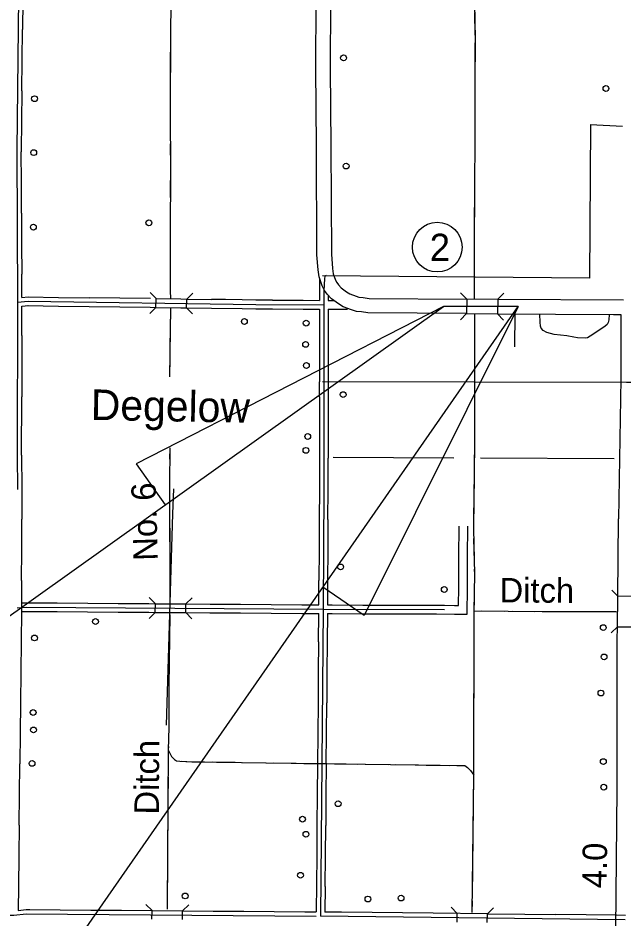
# Model space of a CAD drawing. Extents: x -4306 to 3843, y 131 to 8341.
# Drawn here: x -1926 to -255, y 1950 to 4435 of the extents above; entities that cross this region are included whole.
import ezdxf

# ---------------------------------------------------------------- set-up
doc = ezdxf.new("R2010")
doc.units = 0
for name, color, linetype in [('10', 7, 'Continuous'), ('24', 7, 'Continuous'), ('31', 7, 'Continuous'), ('32', 7, 'Continuous'), ('33', 7, 'Continuous'), ('38', 7, 'Continuous'), ('50', 7, 'Continuous'), ('52', 7, 'Continuous'), ('53', 7, 'Continuous'), ('55', 7, 'Continuous'), ('56', 7, 'Continuous'), ('57', 7, 'Continuous'), ('61', 7, 'Continuous'), ('62', 7, 'Continuous')]:
    doc.layers.add(name, color=color, linetype=linetype)

msp = doc.modelspace()

# ---------------------------------------------------------------- linework, layer by layer
at = {"layer": '10'}
for p, q in [((-1100.3, 3780.5), (-1101.9, 4080.9)), ((-1096.8, 3739), (-1100.3, 3780.5)), ((-1094.3, 3719.7), (-1096.8, 3739)), ((-1086.2, 3695.3), (-1094.3, 3719.7)), ((-1079.5, 3682.8), (-1086.2, 3695.3)), ((-1071.8, 3672), (-1079.5, 3682.8)), ((-1059.8, 3659.7), (-1071.8, 3672)), ((-1040.8, 3645.6), (-1059.8, 3659.7)), ((-686.3, 3658.5), (-686.6, 3618.5)), ((-601.1, 3657.9), (-686.2, 3658.5)), ((-600.7, 3657.9), (-601, 3617.9)), ((-252.8, 3655.5), (-600.7, 3657.9)), ((-1027.4, 3637.4), (-1040.8, 3645.6)), ((-1005, 3628.7), (-1027.4, 3637.4)), ((-991.1, 3624.8), (-1005, 3628.7)), ((-977.5, 3623.7), (-991.1, 3624.8)), ((-959.9, 3620.4), (-977.5, 3623.7)), ((-686.6, 3618.5), (-959.9, 3620.4)), ((-687.1, 3618.5), (-600.9, 3617.9)), ((-601, 3617.9), (-281, 3615.7)), ((-281, 3615.7), (-260.7, 3616)), ((-260.7, 3616), (-260.6, 3613.9)), ((-260.6, 3613.9), (-260.3, 3438.2)), ((-260.3, 3438.2), (-266.6, 3051.5)), ((-269.9, 2753.7), (-269, 2836.4)), ((-229, 2837.7), (-269, 2838.1)), ((-269.9, 2754), (-229.9, 2753.6))]:
    msp.add_line(p, q, dxfattribs=at)
for points in [[(-1101.9, 4080.9), (-1103.3, 4295.8), (-1102.5, 4483.2)], [(-1062.5, 4483.1), (-1063.3, 4295.8), (-1061.9, 4081.1)], [(-1061.9, 4081.1), (-1060.3, 3782.3), (-1057, 3743.3), (-1055.1, 3728.7), (-1049.3, 3711.2), (-1045.5, 3704), (-1041, 3697.8), (-1033.3, 3689.9), (-1018.4, 3678.8), (-1009.5, 3673.4), (-992.3, 3666.7), (-984.1, 3664.3), (-972.2, 3663.4), (-956, 3660.3), (-686.3, 3658.5)], [(-269, 2836.4), (-266.6, 3051.5)], [(-314.4, 293.8), (-314.5, 305.1), (-312.3, 441.3), (-305.4, 600.9), (-302, 628.3), (-293.8, 664.7), (-283.6, 735.2), (-284.1, 861.9), (-282.2, 1054.1), (-278.9, 1201.3), (-280.3, 1434.8), (-278.7, 1599.9), (-273.4, 1758.6), (-274.2, 1917.6), (-271, 2305.4), (-270.3, 2716.6), (-269.9, 2753.7)]]:
    msp.add_lwpolyline(points, dxfattribs=at)
at = {"layer": '31'}
for p, q in [((-1912.7, 4483.5), (-1913.6, 4402.7)), ((-1913.6, 4402.7), (-1913.6, 4402.7)), ((-1915.4, 4233.8), (-1916.2, 4149.3)), ((-1916.2, 4149.3), (-1917.1, 4070.3)), ((-1917.1, 4070.3), (-1917.1, 4065)), ((-1916.5, 3896), (-1916.3, 3811.5)), ((-1916.3, 3811.5), (-1916, 3727)), ((-1916, 3727), (-1916, 3727)), ((-1915.8, 3662.9), (-1898.4, 3664.6)), ((-1898.4, 3664.6), (-1813.9, 3663.4)), ((-1813.9, 3663.4), (-1729.4, 3662.3)), ((-1545.1, 3635.8), (-1544.8, 3659.8)), ((-1544.8, 3659.8), (-1476, 3658.9)), ((-1476, 3658.9), (-1460.2, 3658.7)), ((-1460.5, 3634.7), (-1460.2, 3658.7)), ((-1460.1, 3658.8), (-1391.5, 3657.8)), ((-1222.6, 3655.8), (-1138.1, 3655.3)), ((-1138.1, 3655.3), (-1093, 3654.9)), ((-1069, 3654.8), (-1053, 3654.7)), ((-1915.8, 3638.8), (-1897.4, 3640.6)), ((-1898.7, 3640.5), (-1814.2, 3639.4)), ((-1814.2, 3639.4), (-1729.7, 3638.3)), ((-1560.8, 3636), (-1545.1, 3635.8)), ((-1545, 3635.8), (-1476.3, 3634.9)), ((-1476.3, 3634.9), (-1460.6, 3634.7)), ((-1460.6, 3634.7), (-1391.8, 3633.8)), ((-1222.8, 3631.8), (-1222.8, 3631.8)), ((-1222.8, 3631.8), (-1138.3, 3631.2)), ((-1138.3, 3631.2), (-1093, 3630.9)), ((-1069, 3630.8), (-1015.9, 3630.4)), ((-1915.9, 3558), (-1916, 3473.5)), ((-1916, 3473.5), (-1916.1, 3389)), ((-1093.1, 3388.4), (-1093, 3429.9)), ((-1069, 3429.9), (-1069, 3429.9)), ((-1916.3, 3227.2), (-1916.1, 3389)), ((-1916.1, 3389), (-1916.1, 3389)), ((-1093.1, 3388.4), (-1093.3, 3304)), ((-1069.1, 3388.4), (-1069.3, 3303.9)), ((-1093.3, 3304), (-1093.4, 3219.5)), ((-1069.3, 3303.9), (-1069.4, 3219.4)), ((-1916.3, 3227.2), (-1915.2, 3135.7)), ((-1915.2, 3133.4), (-1915.6, 3051)), ((-1915.2, 3135.7), (-1915.2, 3133.4)), ((-1093.9, 3050.5), (-1094.3, 2966)), ((-1069.9, 3050.4), (-1070.3, 2965.9)), ((-1094.3, 2966), (-1094.7, 2881.5)), ((-1070.3, 2965.9), (-1070.7, 2881.4)), ((-1916.5, 2882), (-1916.8, 2820.3)), ((-1916.8, 2820.3), (-1917, 2796.3)), ((-1917, 2796.3), (-1917.9, 2713)), ((-1095.8, 2712.6), (-1096.5, 2628.1)), ((-1071.8, 2712.4), (-1072.5, 2627.9)), ((-1096.5, 2628.1), (-1097.2, 2543.6)), ((-1072.5, 2627.9), (-1073.2, 2543.4)), ((-1919.6, 2544), (-1920.4, 2459.6)), ((-1920.4, 2459.6), (-1921.3, 2375.1)), ((-1098.7, 2374.7), (-1099.4, 2290.2)), ((-1074.7, 2374.5), (-1075.4, 2290)), ((-1099.4, 2290.2), (-1100.1, 2205.7)), ((-1075.4, 2290), (-1076.1, 2205.5)), ((-1923, 2206.1), (-1923.9, 2121.6)), ((-1100.1, 2205.7), (-1100.1, 2205.7)), ((-1923.9, 2121.6), (-1924.7, 2037.1)), ((-1077.6, 2036.5), (-1078.2, 1966.2)), ((-1032.5, 1965.7), (-1078.2, 1966.2)), ((-948, 1964.8), (-1032.5, 1965.7)), ((-629.3, 1961.2), (-779, 1962.9)), ((-713.1, 1938.1), (-712.8, 1962.1)), ((-629.6, 1937.2), (-629.3, 1961.2)), ((-629.3, 1961.2), (-525.6, 1960)), ((-525.6, 1960), (-441.1, 1959.1)), ((-356.6, 1958.1), (-441.1, 1959.1)), ((-272.1, 1957.2), (-356.6, 1958.1)), ((-247.9, 1956.9), (-272.1, 1957.2))]:
    msp.add_line(p, q, dxfattribs=at)
for points in [[(-1914.5, 4318.3), (-1913.6, 4402.7)], [(-1915.4, 4233.8), (-1914.5, 4318.3)], [(-1916.8, 3980.5), (-1917.1, 4065)], [(-1916.5, 3896), (-1916.8, 3980.5)], [(-1915.8, 3662.9), (-1916, 3727)], [(-1074.7, 3724.2), (-1078.5, 3721.7), (-1079.5, 3714.3), (-1081.3, 3682.4), (-1081.6, 3642.9), (-1081, 3429.9), (-1081.6, 3132.7)], [(-1644.9, 3661.2), (-1729.4, 3662.3)], [(-1560.5, 3660), (-1644.9, 3661.2)], [(-1307, 3656.6), (-1353.3, 3657.3), (-1391.5, 3657.8)], [(-1222.6, 3655.8), (-1268.8, 3656.1), (-1307, 3656.6)], [(-1915.9, 3558), (-1915.8, 3638.8)], [(-1729.7, 3638.3), (-1645.3, 3637.2)], [(-1645.3, 3637.2), (-1560.8, 3636)], [(-1391.8, 3633.8), (-1307.3, 3632.6)], [(-1307.3, 3632.6), (-1269.1, 3632.1), (-1222.8, 3631.8)], [(-1069, 3429.9), (-1069, 3429.9), (-1069.1, 3388.4)], [(-1093.4, 3219.5), (-1093.6, 3135)], [(-1069.6, 3134.9), (-1069.4, 3219.4)], [(-1093.6, 3135), (-1093.6, 3132.7), (-1093.9, 3050.5)], [(-1081.6, 3132.7), (-1083, 2802.2), (-1090.3, 1954.4)], [(-1069.9, 3050.4), (-1069.6, 3132.7), (-1069.6, 3134.9)], [(-1916.1, 2966.5), (-1915.6, 3051)], [(-1916.5, 2882), (-1916.1, 2966.5)], [(-1095, 2814.3), (-1094.7, 2881.5)], [(-1070.7, 2881.4), (-1071, 2814.2)], [(-1095.8, 2712.6), (-1095.1, 2790.3)], [(-1071.1, 2790.2), (-1071.8, 2712.4)], [(-1917.9, 2713), (-1918.7, 2628.5)], [(-1918.7, 2628.5), (-1919.6, 2544)], [(-1097.2, 2543.6), (-1098, 2459.2)], [(-1074, 2459), (-1073.2, 2543.4)], [(-1098, 2459.2), (-1098.7, 2374.7)], [(-1074.7, 2374.5), (-1074, 2459)], [(-1922.2, 2290.6), (-1921.3, 2375.1)], [(-1923, 2206.1), (-1922.2, 2290.6)], [(-1100.1, 2205.7), (-1100.9, 2121.2)], [(-1076.8, 2121), (-1076.1, 2205.5)], [(-1100.9, 2121.2), (-1102.2, 1966.5)], [(-1077.6, 2036.5), (-1076.8, 2121)], [(-1924.7, 2037.1), (-1925.4, 1970.7)], [(-863.5, 1963.8), (-948, 1964.8)], [(-779, 1962.9), (-863.5, 1963.8)]]:
    msp.add_lwpolyline(points, dxfattribs=at)
at = {"layer": '32'}
for p, q in [((-1927.7, 3649.7), (-1898.5, 3652.6)), ((-708, 2946.9), (-707.4, 3031.4)), ((-684, 2946.8), (-683.4, 3031.3)), ((-708.5, 2862.4), (-708, 2946.9)), ((-684.5, 2862.3), (-684, 2946.8)), ((-708.8, 2812.9), (-708.5, 2862.4)), ((-685, 2788.9), (-684.5, 2862.3)), ((-1916.8, 2820.3), (-1818.2, 2819.6)), ((-1818.2, 2819.6), (-1733.7, 2819)), ((-1733.7, 2819), (-1649.2, 2818.4)), ((-1649.2, 2818.4), (-1564.7, 2817.8)), ((-1564.7, 2817.8), (-1546.6, 2817.6)), ((-1546.8, 2793.6), (-1546.6, 2817.6)), ((-1546.6, 2817.6), (-1480.2, 2817.1)), ((-1480.2, 2817.1), (-1462.2, 2817)), ((-1462.4, 2793), (-1462.2, 2817)), ((-1462.3, 2817), (-1395.7, 2816.5)), ((-1395.7, 2816.5), (-1311.2, 2815.9)), ((-1311.2, 2815.9), (-1226.7, 2815.3)), ((-1226.7, 2815.3), (-1142.3, 2814.7)), ((-1142.3, 2814.7), (-1095, 2814.3)), ((-1071, 2814.2), (-1057.8, 2814.1)), ((-1057.8, 2814.1), (-973.3, 2813.9)), ((-973.3, 2813.9), (-888.8, 2813.6)), ((-888.8, 2813.6), (-804.4, 2813.3)), ((-804.4, 2813.3), (-747.6, 2813.1)), ((-747.6, 2813.1), (-719.9, 2813)), ((-719.9, 2813), (-708.8, 2812.9)), ((-1928.9, 2805.9), (-1902.7, 2808.2)), ((-1917, 2796.3), (-1818.3, 2795.6)), ((-1818.3, 2795.6), (-1733.8, 2795)), ((-1733.8, 2795), (-1649.4, 2794.4)), ((-1649.4, 2794.4), (-1564.9, 2793.8)), ((-1564.9, 2793.8), (-1546.8, 2793.6)), ((-1546.9, 2793.6), (-1480.4, 2793.1)), ((-1480.4, 2793.1), (-1462.4, 2793)), ((-1462.6, 2793), (-1395.9, 2792.5)), ((-1395.9, 2792.5), (-1311.4, 2791.9)), ((-1311.4, 2791.9), (-1226.9, 2791.3)), ((-1226.9, 2791.3), (-1142.4, 2790.7)), ((-1142.4, 2790.7), (-1095.1, 2790.3)), ((-1071.1, 2790.2), (-1057.9, 2790.1)), ((-1057.9, 2790.1), (-973.4, 2789.8)), ((-973.4, 2789.8), (-888.9, 2789.6)), ((-888.9, 2789.6), (-770.3, 2789.2)), ((-770.3, 2789.2), (-719.9, 2789)), ((-719.9, 2789), (-685, 2788.9)), ((-1925.4, 1970.7), (-1903.9, 1973)), ((-1903.9, 1973), (-1893.9, 1972.9)), ((-1893.9, 1972.9), (-1809.4, 1972.3)), ((-1809.4, 1972.3), (-1724.9, 1971.6)), ((-1724.9, 1971.6), (-1640.4, 1970.9)), ((-1640.4, 1970.9), (-1555.9, 1970.2)), ((-1556.1, 1946.2), (-1555.9, 1970.2)), ((-1555.9, 1970.2), (-1471.4, 1969.5)), ((-1471.6, 1945.5), (-1471.4, 1969.5)), ((-1471.4, 1969.5), (-1386.9, 1968.8)), ((-1386.9, 1968.8), (-1302.4, 1968.1)), ((-1302.4, 1968.1), (-1218, 1967.4)), ((-1218, 1967.4), (-1133.5, 1966.7)), ((-1133.5, 1966.7), (-1102.2, 1966.5)), ((-248.2, 1944.9), (-1090.3, 1954.4))]:
    msp.add_line(p, q, dxfattribs=at)
for points in [[(-1983.5, 5826.9), (-1984.2, 5591.9), (-1978, 5580.6), (-1963.1, 5563), (-1953.4, 5550.1), (-1949.6, 5541.7), (-1948.4, 5534.6), (-1931.5, 5392.4), (-1927.1, 4704.6), (-1924.6, 4492.3), (-1929.1, 4070.4), (-1927.7, 3649.7), (-1928.3, 3227.1), (-1927.2, 3133.3)], [(-1898.5, 3652.6), (-1268.9, 3644.1)], [(-1268.9, 3644.1), (-1081.6, 3642.9)], [(-1902.7, 2808.2), (-1083, 2802.2), (-747.7, 2801.1)], [(-2400.7, 1957.8), (-1937.5, 1957.3), (-1903.3, 1961)], [(-1903.3, 1961), (-1102.5, 1954.5)]]:
    msp.add_lwpolyline(points, dxfattribs=at)
at = {"layer": '33'}
for p, q in [((-1092.9, 3715.7), (-1093, 3654.9)), ((-1069, 3668.1), (-1069, 3654.8)), ((-1093, 3630.9), (-1093, 3429.9)), ((-1069, 3630.8), (-1069, 3429.9)), ((-553.4, 3617.5), (-554.1, 3527)), ((-483.8, 3594.9), (-484, 3617.1)), ((-293.2, 3615.7), (-293.7, 3601.2)), ((-482.5, 3583.7), (-483.8, 3594.9)), ((-480.7, 3578.1), (-482.5, 3583.7)), ((-303.4, 3583.5), (-338, 3561.3)), ((-297.9, 3588.5), (-303.4, 3583.5)), ((-295.1, 3593.8), (-297.9, 3588.5)), ((-293.7, 3601.2), (-295.1, 3593.8)), ((-475.3, 3571.6), (-480.7, 3578.1)), ((-465.4, 3566.2), (-475.3, 3571.6)), ((-444.9, 3561.1), (-465.4, 3566.2)), ((-410.2, 3557), (-444.9, 3561.1)), ((-390.6, 3553.2), (-410.2, 3557)), ((-338, 3561.3), (-352.7, 3552.1)), ((-380, 3551.9), (-390.6, 3553.2)), ((-358.2, 3551.1), (-380, 3551.9)), ((-352.7, 3552.1), (-358.2, 3551.1))]:
    msp.add_line(p, q, dxfattribs=at)
at = {"layer": '38'}
for p, q in [((-1546.7, 2805.6), (-1546.7, 2805.6)), ((-1462.3, 2805), (-1462.3, 2805))]:
    msp.add_line(p, q, dxfattribs=at)
for points in [[(-1561.4, 3677), (-1544.7, 3659.8)], [(-1460.2, 3658.7), (-1443, 3675.4)], [(-1545, 3635.8), (-1562.2, 3619.1)], [(-1443.8, 3617.5), (-1460.5, 3634.7)], [(-1546.6, 2817.6), (-1563.5, 2834.7)], [(-1445.1, 2833.9), (-1462.2, 2817)], [(-1563.9, 2776.8), (-1546.8, 2793.6)], [(-1462.4, 2793), (-1445.5, 2775.9)], [(-1572.7, 1987.3), (-1555.9, 1970.2)], [(-1471.4, 1969.5), (-1454.3, 1986.3)], [(-729.6, 1979.3), (-712.8, 1962.1)], [(-629.3, 1961.2), (-612.1, 1978)]]:
    msp.add_lwpolyline(points, dxfattribs=at)
at = {"layer": '50'}
for p, q in [((-2855, 2139.1), (-750.7, 3638.5)), ((-2436.2, 918.6), (-544.5, 3638.5)), ((-750.7, 3638.5), (-1599.8, 3203.3)), ((-544.5, 3638.5), (-970, 2784.5)), ((-544.5, 3638.5), (-750.7, 3638.5)), ((-1599.8, 3203.3), (-1519.6, 3090.6)), ((-970, 2784.5), (-1083.5, 2863.4))]:
    msp.add_line(p, q, dxfattribs=at)
msp.add_circle((-767.7, 3802.1), 68.6, dxfattribs=at)
at = {"layer": '52'}
for p, q in [((-1055.1, 3222.1), (-721.9, 3220.4)), ((-648, 3220), (-279.3, 3218.1))]:
    msp.add_line(p, q, dxfattribs=at)
at = {"layer": '53'}
msp.add_line((-344.8, 4140.3), (-256.2, 4135.9), dxfattribs=at)
for points in [[(-344.8, 4140.3), (-347.2, 3716.3)], [(-347.2, 3716.3), (-1085.2, 3722.9)], [(506.8, 3428.7), (-245, 3428.6), (-1084.8, 3430.5)]]:
    msp.add_lwpolyline(points, dxfattribs=at)
at = {"layer": '55'}
msp.add_lwpolyline([(-272.1, 2795.3), (-477.6, 2794.8), (-665.7, 2797)], dxfattribs=at)
at = {"layer": '56'}
for points in [[(-1504.4, 4478.2), (-1505.2, 4388.9), (-1506, 4177.7), (-1505.1, 4012.5), (-1506.2, 3840.6), (-1506.1, 3682.7), (-1505.3, 3659.3)], [(-664.9, 3658.3), (-664.8, 3769), (-664.2, 3999.1), (-663.1, 4070.7), (-663.3, 4248.8), (-662.5, 4377), (-664.1, 4475.7)], [(-662.7, 4387), (-663.7, 4450.4)], [(-1504.9, 4425.4), (-1505.2, 4388.9), (-1505.3, 4362)], [(-662.9, 4302.5), (-662.6, 4365.9)], [(-1505.4, 4340.9), (-1505.7, 4277.5)], [(-663.2, 4218.1), (-663.3, 4248.8), (-663.1, 4281.4)], [(-1505.7, 4256.4), (-1506, 4193)], [(-663.2, 4165.2), (-663.2, 4196.9)], [(-1506, 4171.9), (-1505.6, 4108.6)], [(-663.1, 4133.6), (-663.2, 4165.2)], [(-663.4, 4049.1), (-663.1, 4070.7), (-663.1, 4112.4)], [(-1505.5, 4087.4), (-1505.2, 4024.1)], [(-664.3, 3964.6), (-664.2, 3999.1), (-663.7, 4028)], [(-1505.2, 4002.9), (-1505.4, 3971.3)], [(-1505.4, 3971.3), (-1505.6, 3939.6)], [(-664.5, 3880.1), (-664.3, 3943.5)], [(-1505.7, 3918.5), (-1506.1, 3855.1)], [(-664.7, 3795.6), (-664.5, 3859)], [(-1506.2, 3834), (-1506.2, 3770.6)], [(-664.8, 3711.1), (-664.8, 3769), (-664.8, 3774.5)], [(-1506.1, 3749.5), (-1506.1, 3686.1)], [(-664.9, 3658.3), (-664.9, 3690)], [(-1504.5, 3635.3), (-1507.7, 3443.8)], [(-1504.5, 3635.3), (-1505, 3603.6)], [(-664.2, 3429.5), (-663.8, 3599.9), (-664.2, 3618.3)], [(-663.9, 3566.8), (-663.8, 3599.9), (-664.2, 3618.3)], [(-1505.4, 3582.5), (-1506.5, 3519.1)], [(-664.1, 3482.3), (-663.9, 3545.6)], [(-1506.8, 3498), (-1507.7, 3443.8)], [(-664.2, 3429.5), (-664.2, 3461.2)], [(-665.7, 2797), (-664.4, 2899.3), (-666.9, 3024.6), (-664.2, 3269.6), (-664.2, 3429.5)], [(-664.2, 3356.7), (-664.2, 3420.1)], [(-664.2, 3303.9), (-664.2, 3335.6)], [(-664.2, 3272.2), (-664.2, 3303.9)], [(-1507.1, 3248), (-1507.6, 3146.3), (-1506.3, 2829.3)], [(-1507.1, 3248), (-1507.2, 3216.3)], [(-665.1, 3187.7), (-664.4, 3251.1)], [(-1507.3, 3195.2), (-1507.6, 3146.3), (-1507.5, 3131.8)], [(-666, 3103.2), (-665.3, 3166.6)], [(-1496.8, 3135), (-1498.9, 3065.5)], [(-1507.5, 3110.7), (-1507.2, 3047.3)], [(-666.8, 3018.8), (-666.9, 3024.6), (-666.3, 3082.1)], [(-1498.9, 3065.5), (-1516.5, 2482)], [(-1507.1, 3026.2), (-1506.9, 2962.9)], [(-665.1, 2934.3), (-666.4, 2997.6)], [(-1506.8, 2941.7), (-1506.5, 2878.4)], [(-665, 2849.8), (-664.4, 2899.3), (-664.7, 2913.2)], [(-1506.4, 2857.2), (-1506.3, 2829.3)], [(-665.7, 2797), (-665.3, 2828.7)], [(-1506.6, 2786.8), (-1509.9, 2594.6), (-1509.8, 2476)], [(-1506.6, 2786.8), (-1507.1, 2755.1)], [(-671, 1965), (-666.9, 2343.9), (-665.7, 2797)], [(-276, 2795.3), (-477.6, 2794.8), (-665.7, 2797)], [(-665.7, 2778.2), (-665.7, 2797)], [(-582.3, 2796), (-645.6, 2796.8)], [(-497.8, 2795), (-561.1, 2795.8)], [(-413.3, 2795), (-476.7, 2794.8)], [(-328.8, 2795.2), (-392.2, 2795)], [(-276, 2795.3), (-307.7, 2795.2)], [(-1507.5, 2734), (-1508.6, 2670.6)], [(-666, 2693.7), (-665.8, 2757.1)], [(-666.2, 2609.2), (-666, 2672.6)], [(-1508.9, 2649.5), (-1509.9, 2594.6), (-1509.9, 2586.2)], [(-666.4, 2524.7), (-666.2, 2588.1)], [(-1509.8, 2565), (-1509.8, 2501.7)], [(-666.6, 2471.9), (-666.5, 2503.6)], [(-1509.8, 2476), (-1510.9, 2414), (-1514.5, 1974.3)], [(-1509.8, 2476), (-1510.4, 2444.3)], [(-1509.8, 2480.5), (-1509.8, 2476)], [(-666.7, 2440.2), (-666.6, 2471.9)], [(-1510.7, 2423.2), (-1510.9, 2414), (-1511.3, 2359.8)], [(-1510.9, 2414), (-1501.8, 2396), (-1493.5, 2387.1), (-1488, 2383.9), (-1479.1, 2383), (-1445.5, 2381.2), (-692, 2370.4), (-684, 2365.6), (-675.6, 2357.3), (-666.9, 2343.9)], [(-1510.9, 2414), (-1501.8, 2396), (-1493.9, 2387.6)], [(-666.9, 2355.8), (-666.7, 2419.1)], [(-1473.9, 2382.7), (-1445.5, 2381.2), (-1410.6, 2380.7)], [(-1389.5, 2380.4), (-1326.1, 2379.5)], [(-1305, 2379.2), (-1241.7, 2378.3)], [(-1220.5, 2378), (-1157.2, 2377)], [(-1136.1, 2376.7), (-1072.7, 2375.8)], [(-1051.6, 2375.5), (-1019.9, 2375.1)], [(-1019.9, 2375.1), (-988.2, 2374.6)], [(-967.1, 2374.3), (-903.7, 2373.4)], [(-882.6, 2373.1), (-819.3, 2372.2)], [(-798.1, 2371.9), (-734.8, 2371)], [(-713.7, 2370.7), (-692, 2370.4), (-684, 2365.6), (-675.6, 2357.3), (-666.9, 2343.9)], [(-1511.5, 2338.7), (-1512, 2275.3)], [(-667.7, 2271.3), (-667, 2334.6)], [(-1512.2, 2254.2), (-1512.7, 2190.8)], [(-668.6, 2186.8), (-667.9, 2250.2)], [(-1512.9, 2169.7), (-1513.4, 2106.4)], [(-669.5, 2102.3), (-668.9, 2165.7)], [(-1513.6, 2085.2), (-1514.1, 2021.9)], [(-670.5, 2017.8), (-669.8, 2081.2)], [(-1514.3, 2000.7), (-1514.5, 1974.3)], [(-671, 1965), (-670.7, 1996.7)]]:
    msp.add_lwpolyline(points, dxfattribs=at)
at = {"layer": '57'}
for centre in [(-1026.7, 4324.7), (-301.8, 4240.1), (-1880.5, 4212), (-1882.9, 4063), (-1019.6, 4025.9), (-1564.6, 3869.1), (-1883.8, 3857.4), (-1300.8, 3596.8), (-1130.1, 3592.3), (-1131.4, 3533.5), (-1129.5, 3475.1), (-1027.8, 3394.9), (-1125.7, 3279.3), (-1130.5, 3240.9), (-1034.8, 2919.1), (-748.3, 2856.7), (-1712.2, 2768.2), (-309.1, 2751.5), (-1880.7, 2722.9), (-306.9, 2670.6), (-315.5, 2570.9), (-1884.4, 2517), (-1883.4, 2468.9), (-308.9, 2381.6), (-1887.4, 2376.5), (-307.8, 2311), (-1041.7, 2265.2), (-1140.2, 2222.6), (-1130.5, 2180.8), (-1145.7, 2067.7), (-1464.3, 2010.4), (-959.4, 2002), (-867.8, 2004.7)]:
    msp.add_circle(centre, 8, dxfattribs=at)
at = {"layer": '62'}
for p, q in [((-686.5, 3638.5), (-686.5, 3638.5)), ((-601.3, 3637.9), (-601.3, 3637.9))]:
    msp.add_line(p, q, dxfattribs=at)
for points in [[(-686.3, 3658.5), (-703.2, 3675.6)], [(-584, 3674.7), (-601.1, 3657.9)], [(-703.7, 3601.6), (-686.6, 3618.5)], [(-601.4, 3617.9), (-584.6, 3600.8)], [(-285.7, 2855.3), (-269, 2838.1)], [(-269.9, 2754), (-287, 2737.2)]]:
    msp.add_lwpolyline(points, dxfattribs=at)

# ---------------------------------------------------------------- texts
at = {"layer": '24'}
msp.add_text('Degelow', height=84.49, rotation=358.9554, dxfattribs=at).set_placement((-1725.7, 3325))
at = {"layer": '50'}
msp.add_text('2', height=75.7, dxfattribs=at).set_placement((-788.7, 3763.5))
at = {"layer": '56'}
for s, rotation, p in [('No. 6', 91.7362, (-1539.6, 2937)), ('Ditch', 359.6372, (-595.8, 2821.1)), ('Ditch', 89.7133, (-1537.1, 2235.2))]:
    msp.add_text(s, height=67.59, rotation=rotation, dxfattribs=at).set_placement(p)
at = {"layer": '61'}
msp.add_text('4.0', height=67.59, rotation=89.1807, dxfattribs=at).set_placement((-299.9, 2031.5))

doc.saveas('drawing.dxf')
